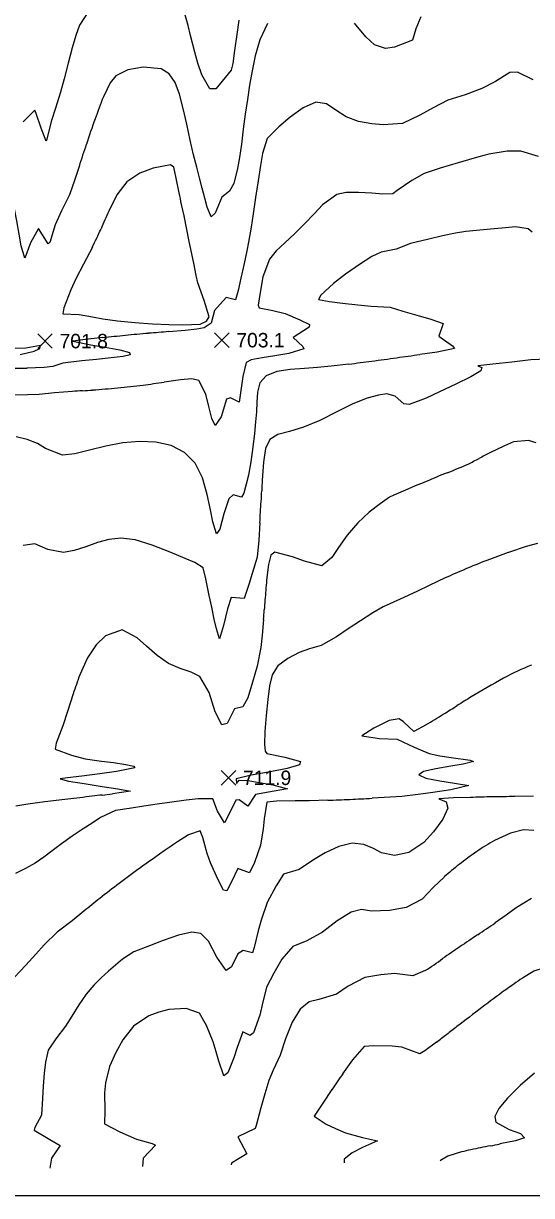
# Model space of a CAD drawing. Extents: x 2566079 to 2571326, y 424054 to 426896.
# Drawn here: x 2567271 to 2567799, y 424077 to 425294 of the extents above; entities that cross this region are included whole.
import ezdxf

# ---------------------------------------------------------------- set-up
doc = ezdxf.new("R2010")
doc.units = 0
for name, color, linetype in [('Contour_ADS_Major', 7, 'Continuous'), ('Contour_ADS_Minor', 7, 'Continuous'), ('Contour_ADS_Spot_Elevation', 7, 'Continuous'), ('Contour_ADS_State_Plane_Border', 7, 'Continuous')]:
    doc.layers.add(name, color=color, linetype=linetype)

# ---------------------------------------------------------------- blocks, each defined once
blk = doc.blocks.new('S750')
at = {"layer": 'Contour_ADS_Spot_Elevation'}
for p, q in [((-0.5, 0.498), (0.5, -0.498)), ((-0.498, -0.5), (0.498, 0.5))]:
    blk.add_line(p, q, dxfattribs=at)

msp = doc.modelspace()

# ---------------------------------------------------------------- linework, layer by layer
at = {"layer": 'Contour_ADS_Major'}
for points in [[(2567684.1, 425301.1), (2567679, 425288.7), (2567675.4, 425276.8), (2567656.9, 425269.6), (2567647.4, 425268.2), (2567636, 425272.2), (2567626.9, 425280.4), (2567615.3, 425294.6)], [(2567524.8, 425294.3), (2567517, 425277.3), (2567512.1, 425260.8), (2567508.8, 425245.1), (2567506.2, 425230.1), (2567503.9, 425215.4), (2567501.8, 425200.2), (2567499.7, 425184.4), (2567497.7, 425168.9), (2567495.7, 425155), (2567493.8, 425143.7), (2567489.8, 425128.2), (2567485.3, 425120), (2567477.4, 425113.8), (2567470.3, 425097.3), (2567466.2, 425093.5), (2567462, 425103.5), (2567459.6, 425112.9), (2567457, 425123.4), (2567454.3, 425133.9), (2567451.3, 425145.1), (2567448, 425158), (2567444.5, 425173.2), (2567440.9, 425189.7), (2567437.2, 425206), (2567433.4, 425220.8), (2567428.8, 425233.1), (2567422.7, 425242), (2567414.5, 425247.1), (2567395.8, 425249), (2567379.7, 425246.2), (2567367.3, 425240), (2567361.4, 425232.5), (2567354.4, 425218.1)], [(2567329.1, 425145.8), (2567324.5, 425131.3), (2567319, 425116.3), (2567310.8, 425099.8), (2567304.3, 425085.2), (2567298.7, 425066.9), (2567297, 425065.3), (2567287, 425081.2), (2567278.5, 425066.6), (2567272.8, 425050.6), (2567268.9, 425063.3), (2567266.8, 425075.5), (2567264.3, 425089.3), (2567262.1, 425101.7), (2567258.9, 425119.3), (2567256.9, 425131.2), (2567254.3, 425144.8)], [(2567804, 424858.7), (2567795.8, 424861.2), (2567780.5, 424859.7), (2567771, 424855.8), (2567755.9, 424848.3)], [(2567651.4, 424802.2), (2567641.9, 424795.6), (2567630.4, 424786.7), (2567618.5, 424775.6), (2567607.7, 424762.8), (2567598.6, 424750.2), (2567591.5, 424739.8), (2567581.4, 424731.2), (2567563.2, 424735.8), (2567550.7, 424740.4), (2567532.5, 424745.4), (2567528.3, 424742.2), (2567525.9, 424732.6), (2567523.9, 424716)], [(2567520.7, 424675.3), (2567519.2, 424659), (2567517.8, 424646.3), (2567514, 424627), (2567509.3, 424610.3), (2567504.4, 424594), (2567499.1, 424584.5), (2567490.5, 424582.7), (2567483, 424567.4), (2567477.3, 424566), (2567470.5, 424579.4), (2567467.3, 424589.4), (2567464.4, 424599.5), (2567454.6, 424616), (2567445.5, 424620.6), (2567434.2, 424624.4), (2567422.1, 424629.6), (2567410.2, 424637.9), (2567399.3, 424647.6), (2567389.6, 424656.3), (2567373.8, 424664.5), (2567356.6, 424658.2), (2567347, 424649.1), (2567337.8, 424635.5), (2567329.8, 424617.7)], [(2567323, 424598.1), (2567317.2, 424579.7), (2567312.1, 424564.9), (2567305.2, 424546.8), (2567304.4, 424540.8), (2567321.1, 424534.5), (2567335.5, 424530.6), (2567352.3, 424528.3), (2567365, 424526.8), (2567377.6, 424524.9), (2567386, 424523), (2567387, 424521.2), (2567368, 424517.4), (2567350.5, 424515), (2567332.1, 424512.7), (2567317.1, 424510.8), (2567309.4, 424509.8), (2567318.2, 424507.4), (2567334.3, 424504.9), (2567353.2, 424501.9), (2567369.5, 424499.3), (2567382.5, 424497), (2567363.7, 424494.2)], [(2567293.5, 424485.9), (2567275.8, 424483.6), (2567263.3, 424481.6)], [(2567799.1, 424385.5), (2567783.2, 424375.8), (2567772.7, 424368.3), (2567761.4, 424360.3)], [(2567688.5, 424310.9), (2567675.7, 424305.3), (2567656.6, 424307.6), (2567642.4, 424306.4), (2567626.1, 424303.4), (2567608.6, 424294.5), (2567596.4, 424286.3), (2567578.3, 424280.8), (2567568, 424278.3), (2567558.9, 424270.8), (2567550.3, 424257.1), (2567543.6, 424239.8), (2567538, 424222.8), (2567530.6, 424207.2), (2567526.3, 424196.6), (2567521.9, 424182.8), (2567517.8, 424168.2), (2567513.1, 424149.8), (2567512, 424146.8), (2567494.1, 424138), (2567503.3, 424120.6), (2567487.4, 424110.6), (2567487.2, 424108.9)]]:
    msp.add_lwpolyline(points, dxfattribs=at)
for centre, radius, start, end in [((2567827.5, 425024.9), 511, 157.7905, 160.5463), ((2568492.2, 424787.2), 1216.9, 160.4149, 161.7269), ((2569226.8, 424540.6), 1991.9, 161.6161, 162.3101), ((2568617.6, 423143.7), 1910.1, 116.8182, 117.1993), ((2567547.2, 425255), 457.8, 291.0161, 293.9737), ((2567530.7, 425247.4), 457.9, 296.2536, 297.8441), ((2568861.2, 422017.3), 3036.5, 112.2496, 112.6954), ((2568297.7, 423356.7), 1583.4, 112.5849, 114.0876), ((2569240.7, 424561.9), 1723.7, 174.8728, 175.5583), ((2570396.1, 424470.4), 2882.7, 175.5228, 175.7233), ((2565914.6, 424803.4), 1611.2, 355.4395, 355.798), ((2567788.1, 424447.8), 488.8, 159.6596, 162.0891), ((2569694.8, 404538.2), 20091.7, 96.72305, 96.75949), ((2569677.5, 404530.3), 20097.6, 96.64109, 96.67134), ((2567280.6, 425160.1), 671, 276.2098, 277.1151), ((2567904, 419557.7), 4965.8, 96.7851, 97.0618), ((2568216.5, 416935.9), 7606.2, 96.69314, 96.7894), ((2566871.4, 425657.3), 1573, 303.6559, 304.4592), ((2575945.4, 412200.8), 14657.1, 124.02904, 124.11522), ((2575955.8, 412216.1), 14650.3, 124.18222, 124.26816), ((2567611.6, 424443.5), 153.3, 300.1324, 308.3474)]:
    msp.add_arc(centre, radius, start, end, dxfattribs=at)
at = {"layer": 'Contour_ADS_Minor'}
for p, q in [((2567351.9, 425080.8), (2567351.9, 425080.8)), ((2567801.3, 424492), (2567781.9, 424491.6))]:
    msp.add_line(p, q, dxfattribs=at)
for points in [[(2567340, 425308.3), (2567329.6, 425292.5), (2567325.6, 425281.9), (2567321.9, 425268.8), (2567317.8, 425252.9), (2567313.7, 425236.7), (2567309.9, 425222.8), (2567304.5, 425206.4), (2567300, 425192.4), (2567295.6, 425174), (2567294.9, 425171.9), (2567289.8, 425185.5), (2567284.5, 425200.6), (2567283.1, 425204.3), (2567271, 425192.1)], [(2567494.9, 425297.8), (2567492.9, 425282.9), (2567490.7, 425266.3), (2567488.7, 425252.8), (2567487.1, 425245.7), (2567474.5, 425230.7), (2567471, 425226.4), (2567464.9, 425226.4), (2567456.7, 425240.9), (2567452.6, 425253.1), (2567449.2, 425264.6), (2567445, 425281.7), (2567442.3, 425292.1), (2567438.3, 425306.8)], [(2567800.8, 425235.6), (2567784.4, 425243.7), (2567776.7, 425243.3), (2567761.8, 425233.9), (2567747.4, 425226.6), (2567730.1, 425220.3), (2567712.1, 425214.6), (2567696.8, 425206.8)], [(2567696.8, 425206.8), (2567682.9, 425199.1), (2567665, 425190.4), (2567645.1, 425189.1), (2567633.2, 425190), (2567619.5, 425192.5), (2567606.4, 425197.3), (2567595.7, 425204.4), (2567586, 425210.8), (2567575.2, 425212.4), (2567562, 425206.7), (2567548.2, 425196.8), (2567536.5, 425186.8), (2567524.5, 425174.9), (2567519.6, 425159.3), (2567517.4, 425146.6), (2567515, 425131), (2567512.4, 425113.5), (2567509.8, 425096.5), (2567507.7, 425082.7), (2567505.2, 425067), (2567503.4, 425058.3), (2567500.6, 425044.9), (2567497.3, 425029.8), (2567494.5, 425017), (2567491.6, 425007.4), (2567482, 425009.8), (2567469.9, 424996.2), (2567466.3, 424982.9), (2567459.1, 424978.3), (2567451.5, 424976.8), (2567439.2, 424975.5), (2567422.2, 424974.2)], [(2567806.3, 425156.2), (2567788, 425161.7), (2567773.7, 425161.8), (2567754.8, 425158.5), (2567744.3, 425155.8), (2567733.5, 425152.7), (2567722.9, 425149.5), (2567704.2, 425144.1), (2567687.7, 425138.4), (2567674.9, 425131.3), (2567659.6, 425120.8), (2567655.1, 425117.3), (2567644.7, 425117.1), (2567633.1, 425118), (2567619.3, 425118.8), (2567606.4, 425118.6), (2567596.7, 425116.7), (2567582, 425105.9), (2567573.3, 425096.7), (2567563.4, 425086.1), (2567553, 425075.7), (2567542.9, 425066.5), (2567534, 425058.1), (2567526.9, 425049.5), (2567519.9, 425031), (2567517.3, 425014.9), (2567515.2, 425001.8), (2567516.2, 424999), (2567530.4, 424996.1), (2567543.2, 424993), (2567558.5, 424986.4), (2567568.5, 424981.6), (2567568.2, 424978.8), (2567551.6, 424968), (2567561.6, 424958.8), (2567562.5, 424956.5), (2567547, 424951.6), (2567532.4, 424949.2), (2567519.4, 424947.2), (2567507.7, 424945.1), (2567502.7, 424942.2), (2567499.2, 424927.8), (2567497.3, 424913.1), (2567495.5, 424900.9), (2567486.5, 424905.4), (2567482.4, 424904.2), (2567476.7, 424885.8), (2567470.4, 424876.9), (2567467, 424884.1), (2567463.8, 424896.6), (2567460.7, 424909.4), (2567453.5, 424923.6), (2567446.2, 424925.3), (2567434.3, 424924.3), (2567417.5, 424921.8)], [(2567433.1, 425118.3), (2567429.9, 425133.5), (2567427.4, 425145.2), (2567423.9, 425147.4), (2567406.2, 425143.9), (2567392.2, 425138.7), (2567378.8, 425129.8), (2567368.3, 425116.3), (2567360, 425099.4)], [(2567342.9, 425062), (2567333.8, 425044.4), (2567325.9, 425029.2), (2567320.4, 425017.5), (2567313.1, 424999), (2567312.4, 424992.9), (2567329.3, 424992.1), (2567342.9, 424989.6), (2567353.7, 424987.6), (2567368.9, 424985.6), (2567387, 424983.8), (2567405.5, 424982.4), (2567422.5, 424981.5), (2567436.9, 424981.2), (2567455, 424982.1), (2567461.5, 424985), (2567464.4, 424989.7), (2567459.1, 425006.6), (2567452.6, 425024.8), (2567450.9, 425032.7), (2567448.2, 425045.4), (2567443.6, 425067.7), (2567438.1, 425094.5), (2567435.6, 425106.4)], [(2567799.7, 425077.5), (2567795.5, 425081), (2567782.4, 425083), (2567772, 425082.2), (2567760.4, 425081), (2567749.3, 425079.8), (2567731, 425078.1), (2567720.2, 425076.5), (2567706.7, 425073.8), (2567692.4, 425070.4), (2567673.5, 425065.7), (2567658.4, 425059.8), (2567642.8, 425056.6), (2567633.3, 425052.3), (2567620.3, 425044), (2567606, 425033.8), (2567593.4, 425024.1), (2567580.1, 425012.1), (2567577.9, 425007.5), (2567589.1, 425005.4), (2567602.7, 425003.8), (2567618.6, 425002), (2567632.4, 425000.6), (2567652.1, 424999.8), (2567665.4, 424995.6), (2567682.3, 424990.8), (2567693.6, 424987.5), (2567707.3, 424982.7), (2567702.7, 424969.4), (2567717.1, 424959.6), (2567719, 424956.6), (2567701.1, 424953.1), (2567682.9, 424950.6)], [(2567353.9, 424968), (2567335.8, 424966.1), (2567322.7, 424964.5), (2567341.3, 424960.5), (2567356.1, 424958), (2567371.3, 424955.2), (2567381.4, 424952.5), (2567382.2, 424950.3), (2567375, 424948.5), (2567362.5, 424946.9), (2567347.2, 424945.4), (2567332, 424943.9), (2567312.4, 424941.6), (2567301.8, 424938.2), (2567292.9, 424936.9), (2567275, 424936.4)], [(2567268, 424950.6), (2567282.5, 424953.9), (2567288.2, 424956.8), (2567289.2, 424960), (2567273.9, 424957.2), (2567261.4, 424956.8)], [(2567815.4, 424945.8), (2567798.2, 424945.1), (2567778.6, 424942.4), (2567759, 424940.4), (2567743.3, 424938.7), (2567747.6, 424936.9), (2567746.3, 424933.6), (2567736.2, 424927.4), (2567720.3, 424919.6), (2567703.5, 424911.7), (2567689.8, 424905.2), (2567671.9, 424898.7), (2567666.5, 424899.2), (2567657.5, 424907.2), (2567648.9, 424909.6), (2567640.2, 424908.4), (2567628.2, 424905), (2567613.5, 424899.2), (2567596.7, 424890.9), (2567579.1, 424882.1), (2567562.3, 424874.9), (2567547.6, 424870.7), (2567535.7, 424867.5), (2567527.3, 424862.4), (2567522.6, 424852.9), (2567520.5, 424838.7), (2567519.4, 424820.1)], [(2567609.3, 424940.5), (2567591.1, 424938.3), (2567576.7, 424936.9), (2567563.2, 424936), (2567548.5, 424935), (2567534.4, 424932.9), (2567523.3, 424928.4), (2567517, 424921), (2567514.5, 424911.4), (2567513.8, 424901.1), (2567513.3, 424891.1), (2567512.5, 424880.7), (2567511.3, 424868.6), (2567509.6, 424854.3), (2567507.4, 424839.2), (2567505, 424825.3), (2567500.1, 424806.6), (2567497.7, 424802.3), (2567489, 424804.8), (2567484.6, 424800.7), (2567479.5, 424785), (2567475.3, 424769.1), (2567472, 424764.2), (2567468.2, 424776.6), (2567465.7, 424789.2), (2567462.3, 424805.2), (2567457.3, 424822.3), (2567449.6, 424837.5), (2567438.5, 424848.8), (2567424.6, 424855.9), (2567408.8, 424859.6), (2567391.9, 424860.3), (2567374.4, 424858.8), (2567356.9, 424855.4), (2567340, 424851.1), (2567324.7, 424847.3), (2567312, 424846), (2567294.4, 424853), (2567285.8, 424858.1), (2567275.2, 424862.2), (2567263.8, 424864.9)], [(2567322.2, 424912.1), (2567303.6, 424910.7), (2567287.8, 424909.1), (2567275.6, 424908.5), (2567259.6, 424908.3), (2567240.2, 424908.3)], [(2567516.9, 424775.6), (2567515.8, 424757.7), (2567514, 424740.1), (2567509, 424723.1), (2567505.5, 424711.7), (2567500.6, 424697), (2567487.1, 424698.3), (2567483.4, 424686.3), (2567479.1, 424669.1), (2567475.1, 424655.2), (2567471.7, 424665.5), (2567469.5, 424675.8), (2567466.9, 424688.2), (2567464.3, 424700.4), (2567460.7, 424717.7), (2567458, 424728.8), (2567449.2, 424734.4), (2567439.3, 424738.8), (2567423.8, 424745.4), (2567405.2, 424752.6), (2567387.2, 424758), (2567372.4, 424759.8), (2567360, 424758.5), (2567348.3, 424755.2), (2567336, 424750.9), (2567323.9, 424747), (2567313, 424744.9), (2567296.6, 424748.1), (2567283, 424753.8), (2567271.1, 424752.2)], [(2567805.2, 424754.3), (2567793.4, 424751.2), (2567775, 424744.9)], [(2567709.5, 424718.5), (2567692.8, 424710.6), (2567679.9, 424704.3), (2567662.6, 424696.3), (2567645.1, 424688.5), (2567634.1, 424682.1), (2567621.5, 424674.1), (2567608.5, 424665.5), (2567596.5, 424657.4), (2567580.6, 424648.4), (2567568.4, 424644.9), (2567557.8, 424640.9), (2567545.9, 424634.9), (2567535.7, 424627.1), (2567529.7, 424617.8), (2567526.8, 424606.4), (2567525.3, 424592.4), (2567523.6, 424575.7), (2567522.2, 424559.1), (2567521.6, 424545.9), (2567522.5, 424538.7), (2567524.2, 424536), (2567542.8, 424532.2), (2567559.1, 424527.7), (2567558, 424524.4), (2567545.1, 424520.5), (2567525.8, 424516.7), (2567508, 424513.8), (2567492.2, 424509.9), (2567492.6, 424505.1), (2567495.3, 424508.5), (2567504.5, 424508), (2567516.6, 424506), (2567530.5, 424503.5), (2567545.6, 424499.5), (2567526, 424495.9), (2567512.2, 424493.5), (2567504.3, 424481.3), (2567495.4, 424488.2), (2567491.8, 424487.7), (2567483.5, 424470.8), (2567480.1, 424464.2), (2567473, 424476.3), (2567467.9, 424489), (2567452.8, 424489.1), (2567440.4, 424487.6), (2567422.9, 424485.2), (2567410.1, 424483.4), (2567396.2, 424481.3), (2567383.5, 424479.4), (2567367, 424476.8), (2567351.4, 424469.7), (2567342.7, 424463.8), (2567333.4, 424457.8), (2567322.1, 424450.3), (2567310.8, 424442.5), (2567301.1, 424435.2), (2567292.4, 424428.5), (2567283.5, 424422.4), (2567273.6, 424416.7), (2567263.2, 424411.4)], [(2567689.7, 424566.1), (2567676.7, 424558.9), (2567666.2, 424569.1), (2567661.6, 424572), (2567651.3, 424570.5), (2567635.2, 424562.6), (2567622.8, 424554.6), (2567641.2, 424551.7), (2567659.6, 424550.9), (2567677.1, 424542.8), (2567692.7, 424536.3), (2567703.9, 424533.9), (2567715.7, 424532), (2567735.2, 424529.2), (2567738.9, 424527.9), (2567728, 424525.1), (2567715.2, 424523.1), (2567699.7, 424520.4), (2567686.7, 424517.3), (2567682, 424514), (2567689.4, 424510.7), (2567704, 424507.8), (2567719.1, 424505.5), (2567733.9, 424503), (2567715.3, 424498.4), (2567696.6, 424495.6), (2567681.2, 424493.5), (2567664.2, 424491.5), (2567652.4, 424490.8), (2567633.5, 424489.7)], [(2567735.7, 424490.6), (2567718.1, 424490.1), (2567702.8, 424489.2), (2567710.3, 424485.8), (2567712.1, 424479.3), (2567706.9, 424468), (2567697.3, 424454.9), (2567687.2, 424443.7), (2567671.5, 424433.4), (2567656.6, 424430.1), (2567643.4, 424433), (2567634.9, 424437.5), (2567624.8, 424441.8), (2567612.8, 424443.2), (2567599, 424439.7), (2567584.9, 424433), (2567572.7, 424425.7), (2567557.7, 424415.6), (2567541.4, 424410.8), (2567533.9, 424398.8), (2567524.4, 424381.5), (2567518.1, 424363.2), (2567515.2, 424351.9), (2567510.9, 424334.8), (2567509.1, 424329.2), (2567499.7, 424331.5), (2567494.1, 424328.1), (2567487.3, 424314.8), (2567481.9, 424310.9), (2567472.2, 424324.7), (2567463.4, 424341.3), (2567455.5, 424349.3), (2567446.2, 424350.5), (2567432.3, 424347.5), (2567416.4, 424342), (2567402.3, 424336.5), (2567386.1, 424330.1), (2567374.3, 424322.5), (2567359.8, 424310), (2567352.1, 424303.2), (2567344.3, 424295.6), (2567336.6, 424286.4), (2567328.8, 424275.2), (2567321.5, 424263.5), (2567314.9, 424253.1), (2567305.1, 424239.9), (2567297.1, 424228), (2567294.3, 424215.8), (2567292.9, 424204.2), (2567291.8, 424190.7), (2567291.1, 424177.9), (2567290.1, 424160.6), (2567283.3, 424147.7), (2567282.6, 424144.9), (2567298.8, 424135.2), (2567309.5, 424129.1), (2567300.4, 424115.8), (2567298.9, 424105.4)], [(2567587.5, 424487.6), (2567568.3, 424487.1), (2567553.4, 424486.9), (2567534.3, 424486.6), (2567524.1, 424485.5), (2567521.2, 424468.2), (2567520.4, 424457.9), (2567517.7, 424441.1), (2567511.4, 424423.1), (2567506, 424412.3), (2567493.9, 424416.8), (2567487.4, 424402.9), (2567482.6, 424393.5), (2567479.2, 424394.1), (2567473.6, 424404.9), (2567465.7, 424422.5), (2567462.3, 424432.3), (2567457.6, 424449), (2567454.8, 424455.7), (2567442.9, 424451.6), (2567431.5, 424444.4)], [(2567801.6, 424456.1), (2567790.9, 424456.9), (2567777.1, 424453.6), (2567760.6, 424445.9)], [(2567708.4, 424407.9), (2567697.2, 424397.5), (2567685.4, 424384.8), (2567668.8, 424376.3), (2567651.6, 424373.1), (2567632.9, 424372.5), (2567622.4, 424374.1), (2567611.8, 424371.4), (2567597.1, 424362.3), (2567582.1, 424350.7), (2567565.8, 424341.7), (2567551.1, 424335.6), (2567539.6, 424322.7), (2567531.4, 424308), (2567523.9, 424293.6), (2567519.3, 424275.2), (2567516.7, 424264.4), (2567510.4, 424246), (2567506.9, 424243.4), (2567499.2, 424247.2), (2567493.3, 424231), (2567489.9, 424220), (2567483.6, 424204.5), (2567479.6, 424201.4), (2567474.2, 424216.6), (2567471.6, 424226.5), (2567468.4, 424236.8), (2567461.5, 424253.8), (2567454.1, 424266.4), (2567440.5, 424271.3), (2567422.5, 424270.4), (2567411.8, 424267.7), (2567401.6, 424263.8), (2567385.7, 424252.9), (2567374.7, 424238.8), (2567367.4, 424225.5), (2567360.6, 424211.1), (2567356.5, 424194), (2567355.4, 424183.9), (2567355.7, 424165.3), (2567355.4, 424151.7), (2567371.4, 424143.2), (2567388.6, 424135.8), (2567405.2, 424131.2), (2567408.5, 424129.4), (2567395.8, 424115.8), (2567395.1, 424107.2)], [(2567923.3, 424404.3), (2567911.7, 424392.7), (2567903.3, 424385.3), (2567889, 424381.8), (2567885.7, 424370.9), (2567885.3, 424358.8), (2567885.2, 424345.2), (2567884.8, 424332.2), (2567884, 424321), (2567878.2, 424302.3), (2567871.1, 424288.4), (2567867.6, 424279.2), (2567860, 424278.2), (2567851.3, 424263.5), (2567847.2, 424254.4), (2567844.1, 424253.5), (2567835.9, 424267.9), (2567829.8, 424281.8), (2567823.4, 424296.9), (2567817.5, 424308.8), (2567809, 424312.6), (2567801.4, 424310), (2567789.6, 424303)], [(2567334, 424372.3), (2567321.8, 424362.3), (2567306.3, 424350.7), (2567292.8, 424337.5), (2567284.1, 424327.9), (2567273.8, 424316.5), (2567262.1, 424303.9), (2567250.7, 424291.3), (2567241.3, 424280.2), (2567231.5, 424265.6), (2567225.3, 424250.1), (2567219.7, 424231.6), (2567216.2, 424219.5), (2567212.6, 424206.6), (2567209.5, 424193.3), (2567207.2, 424179.9), (2567206.1, 424166.9), (2567205.8, 424155.5), (2567204.2, 424138.5), (2567218.7, 424132.2), (2567225.6, 424126.4), (2567218.6, 424117.1), (2567203.3, 424108.6), (2567188.8, 424103.4)], [(2567700.4, 424236.3), (2567688.3, 424227.3), (2567683, 424224.4), (2567664.5, 424231.1), (2567654.4, 424232.2), (2567634.8, 424232.7), (2567625.2, 424231.8), (2567613, 424218), (2567602.9, 424203.6)], [(2567802, 424204.1), (2567787.4, 424191.5), (2567774.2, 424178.2), (2567765.1, 424167.4), (2567760.9, 424159.2), (2567761.9, 424153.2), (2567775.8, 424145.8), (2567787.5, 424141.4), (2567791.7, 424137.2), (2567782.3, 424133.9), (2567766.3, 424130.8)], [(2567591.6, 424187.1), (2567582.2, 424173), (2567573.3, 424159.6), (2567585.8, 424151.3), (2567595.5, 424146.6), (2567605.8, 424142.4), (2567623.6, 424137.5), (2567639.1, 424134.1), (2567623.5, 424126.9), (2567612.8, 424121.6), (2567604.5, 424114.8), (2567604.4, 424111)], [(2567726.5, 424122.4), (2567712.2, 424117.9), (2567704.4, 424113.5), (2567704.3, 424112.8)]]:
    msp.add_lwpolyline(points, dxfattribs=at)
for centre, radius, start, end in [((2557315.3, 423012), 10334.7, 11.69229, 11.75967), ((2568052.1, 424787.9), 759, 155.7649, 157.2965), ((2566115.1, 425663.3), 1367.1, 333.9071, 334.7812), ((2567790.2, 420695.2), 4294.9, 95.5181, 95.8298), ((2567624.3, 422417.1), 2565.1, 94.9897, 95.5283), ((2568188.7, 415352.7), 9652, 94.55451, 94.67988), ((2567225.8, 427938.5), 3022.4, 277.2903, 277.7439), ((2566642.2, 432218.9), 7342.5, 277.75609, 277.96098), ((2566245, 435101.1), 10251.9, 277.92839, 277.99577), ((2566507.1, 433264.5), 8396.7, 277.968, 278.05028), ((2567274.5, 426159.9), 1223.5, 268.6893, 270.0254), ((2567283.2, 425845), 933.1, 275.2943, 276.9167), ((2567203.1, 426346), 1440.2, 277.6783, 278.56), ((2567568.4, 421564.2), 3357, 94.0277, 94.206), ((2567199.2, 426840), 1931.8, 273.962, 274.2718), ((2567225.4, 426465.6), 1556.4, 274.3356, 275.3039), ((2563038.7, 425041.3), 4486.2, 356.8891, 357.0312), ((2571984.5, 424577.4), 4471.7, 176.8889, 177.0314), ((2562657.4, 425068.7), 4868.3, 356.5493, 356.8115), ((2568059.1, 423943.5), 850.3, 111.1315, 112.791), ((2568048.4, 423978.1), 814.2, 109.625, 111.3076), ((2568029.7, 424015.6), 772.4, 112.8475, 114.4884), ((2567887.6, 424400.3), 244.2, 111.2369, 118.7839), ((2568160, 423900.8), 813.2, 118.6602, 121.3908), ((2568372.6, 423550.8), 1222.7, 121.3529, 122.1525), ((2563917.4, 430714.2), 7213.1, 301.53198, 301.69744), ((2560329.8, 436514), 14032.9, 301.71785, 301.78752), ((2568143.6, 407212), 17283.3, 91.19939, 91.23836), ((2567511.8, 426632.3), 2146, 272.0196, 272.6315), ((2567473.3, 427504.2), 3018.8, 272.6032, 273.0425), ((2567876.5, 418601.9), 5890.3, 91.25947, 91.36971), ((2568098.4, 409424.5), 15070.5, 91.29304, 91.33613), ((2568084.7, 409427.1), 15067.5, 91.19653, 91.24122), ((2567914.1, 423715.2), 874.5, 123.4975, 124.8781), ((2567871, 424250.2), 224.7, 119.4197, 124.9602), ((2568164.4, 423350.9), 1316.4, 124.7488, 125.8811), ((2567936, 424153.4), 341.3, 124.6006, 128.3999), ((2567941.1, 424143.4), 352.4, 128.0323, 131.333), ((2568140.5, 423380.1), 1278.8, 125.7795, 127.0052), ((2568111.5, 423422.6), 1227.4, 127.1195, 128.3062), ((2568379.9, 423085.8), 1658, 128.3682, 129.1098), ((2568108.6, 423830.4), 570.1, 124.0164, 126.2009), ((2568985, 422639.8), 2048.6, 126.3137, 127.1614), ((2573800.3, 416304.9), 10005.8, 127.22333, 127.40988), ((2577929.9, 410881.7), 16822.3, 127.36056, 127.40617), ((2566829.7, 425385.5), 1441.7, 307.1512, 307.6835), ((2570058.6, 422519.7), 2977.5, 145.5615, 145.9465), ((2567843.2, 423649.8), 486.8, 101.5181, 103.8747), ((2567896, 423392.5), 749.4, 100.7516, 101.5425), ((2564084.8, 442806.2), 19034.9, 281.12072, 281.15189)]:
    msp.add_arc(centre, radius, start, end, dxfattribs=at)
at = {"layer": 'Contour_ADS_State_Plane_Border'}
msp.add_lwpolyline([(2566079.3, 424077.1), (2571302.9, 424077.1), (2571302.9, 426873.7), (2566079.3, 426873.7), (2566079.3, 424077.1)], close=True, dxfattribs=at)

# ---------------------------------------------------------------- block references
at = {"layer": 'Contour_ADS_Spot_Elevation', "xscale": 15, "yscale": 15}
for p in [(2567293.8, 424964.4), (2567477.4, 424965.4), (2567484.3, 424510.9)]:
    msp.add_blockref('S750', p, dxfattribs=at)

# ---------------------------------------------------------------- texts
at = {"layer": 'Contour_ADS_Spot_Elevation'}
for s, p in [('701.8', (2567308.8, 424956.9)), ('703.1', (2567492.4, 424957.9)), ('711.9', (2567499.3, 424503.4))]:
    msp.add_text(s, height=15, dxfattribs=at).set_placement(p)

doc.saveas('drawing.dxf')
